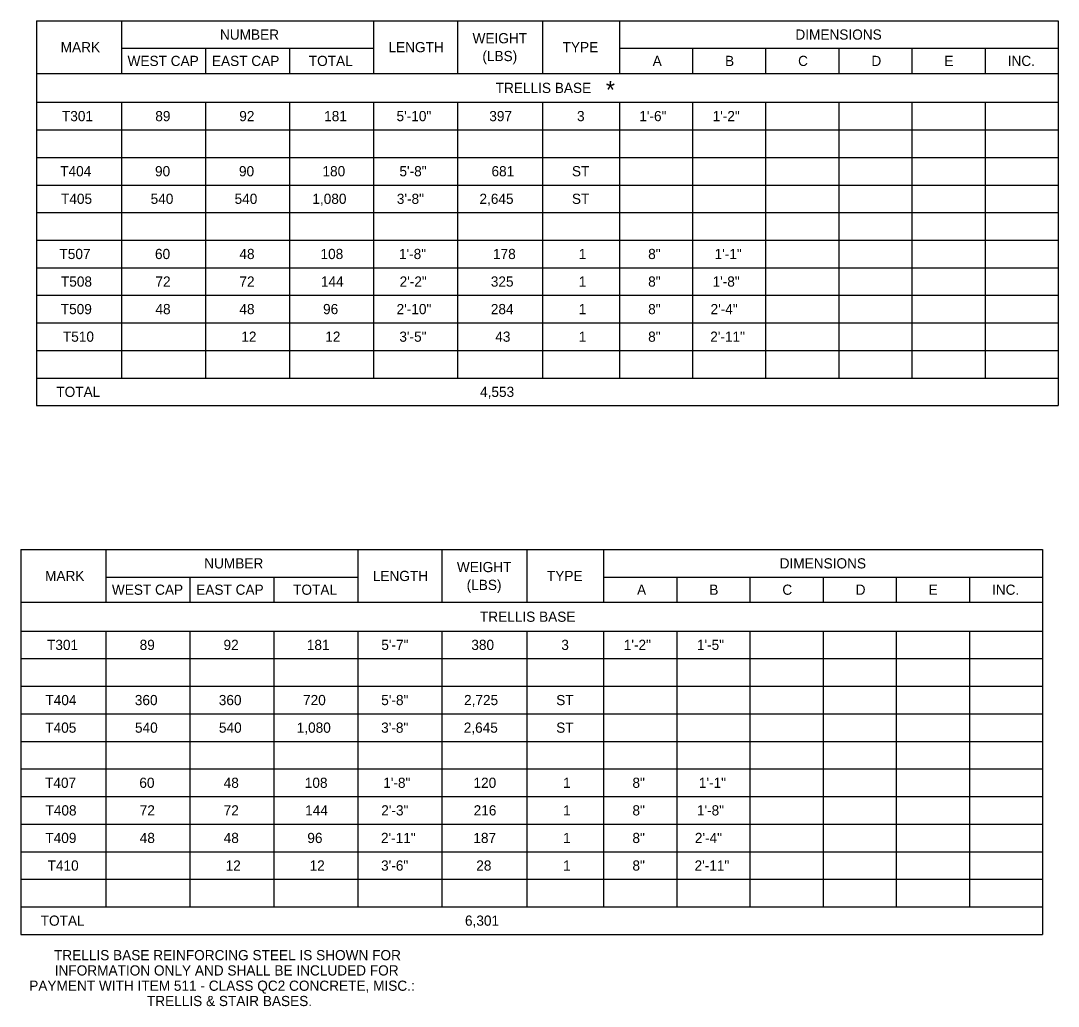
# Model space of a CAD drawing. Extents: x -47.5 to 51.5, y 0.9 to 23.7.
# Drawn here: x 37.25 to 51.5, y 10.13 to 23.67 of the extents above; entities that cross this region are included whole.
import ezdxf

# ---------------------------------------------------------------- set-up
doc = ezdxf.new("R2010")
doc.units = 0
for name, color, linetype in [('BR_P_Gen_Text', 7, 'Continuous'), ('BR_X_Slab_Const_Joint', 7, 'Continuous'), ('BR_X_Slab_Object', 7, 'Continuous')]:
    doc.layers.add(name, color=color, linetype=linetype)

msp = doc.modelspace()

# ---------------------------------------------------------------- linework, layer by layer
at = {"layer": 'BR_X_Slab_Object'}
for p, q in [((37.463, 23.668), (51.496, 23.668)), ((37.463, 23.668), (37.463, 18.381)), ((38.632, 23.668), (38.632, 22.943)), ((42.091, 23.668), (42.091, 22.943)), ((43.244, 23.668), (43.244, 22.943)), ((44.414, 23.668), (44.414, 22.943)), ((45.468, 23.668), (45.468, 22.943)), ((51.496, 23.668), (51.496, 18.381)), ((38.632, 23.289), (42.091, 23.289)), ((39.785, 23.289), (39.785, 22.943)), ((40.938, 23.289), (40.938, 22.943)), ((45.468, 23.289), (51.496, 23.289)), ((46.472, 23.289), (46.472, 22.943)), ((47.477, 23.289), (47.477, 22.943)), ((48.482, 23.289), (48.482, 22.943)), ((49.486, 23.289), (49.486, 22.943)), ((50.491, 23.289), (50.491, 22.943)), ((37.463, 22.943), (51.496, 22.943)), ((37.463, 22.548), (51.496, 22.548)), ((38.632, 22.548), (38.632, 18.76)), ((39.785, 22.548), (39.785, 18.76)), ((40.938, 22.548), (40.938, 18.76)), ((42.091, 22.548), (42.091, 18.76)), ((43.244, 22.548), (43.244, 18.76)), ((44.414, 22.548), (44.414, 18.76)), ((45.468, 22.548), (45.468, 18.76)), ((46.472, 22.548), (46.472, 18.76)), ((47.477, 22.548), (47.477, 18.76)), ((48.482, 22.548), (48.482, 18.76)), ((49.486, 22.548), (49.486, 18.76)), ((50.491, 22.548), (50.491, 18.76)), ((37.463, 22.169), (51.496, 22.169)), ((37.463, 21.79), (51.496, 21.79)), ((37.463, 21.411), (51.496, 21.411)), ((37.463, 21.032), (51.496, 21.032)), ((37.463, 20.654), (51.496, 20.654)), ((37.463, 20.275), (51.496, 20.275)), ((37.463, 19.896), (51.496, 19.896)), ((37.463, 19.517), (51.496, 19.517)), ((37.463, 19.138), (51.496, 19.138)), ((37.463, 18.76), (51.496, 18.76)), ((37.463, 18.381), (51.496, 18.381)), ((37.247, 16.403), (51.28, 16.403)), ((37.247, 16.403), (37.247, 11.116)), ((38.417, 16.403), (38.417, 15.679)), ((41.875, 16.403), (41.875, 15.679)), ((43.028, 16.403), (43.028, 15.679)), ((44.198, 16.403), (44.198, 15.679)), ((45.252, 16.403), (45.252, 15.679)), ((51.28, 16.403), (51.28, 11.116)), ((38.417, 16.025), (41.875, 16.025)), ((39.57, 16.025), (39.57, 15.679)), ((40.723, 16.025), (40.723, 15.679)), ((45.252, 16.025), (51.28, 16.025)), ((46.257, 16.025), (46.257, 15.679)), ((47.261, 16.025), (47.261, 15.679)), ((48.266, 16.025), (48.266, 15.679)), ((49.271, 16.025), (49.271, 15.679)), ((50.275, 16.025), (50.275, 15.679)), ((37.247, 15.679), (51.28, 15.679)), ((37.247, 15.283), (51.28, 15.283)), ((38.417, 15.283), (38.417, 11.495)), ((39.57, 15.283), (39.57, 11.495)), ((40.723, 15.283), (40.723, 11.495)), ((41.875, 15.283), (41.875, 11.495)), ((43.028, 15.283), (43.028, 11.495)), ((44.198, 15.283), (44.198, 11.495)), ((45.252, 15.283), (45.252, 11.495)), ((46.257, 15.283), (46.257, 11.495)), ((47.261, 15.283), (47.261, 11.495)), ((48.266, 15.283), (48.266, 11.495)), ((49.271, 15.283), (49.271, 11.495)), ((50.275, 15.283), (50.275, 11.495)), ((37.247, 14.905), (51.28, 14.905)), ((37.247, 14.526), (51.28, 14.526)), ((37.247, 14.147), (51.28, 14.147)), ((37.247, 13.768), (51.28, 13.768)), ((37.247, 13.389), (51.28, 13.389)), ((37.247, 13.01), (51.28, 13.01)), ((37.247, 12.632), (51.28, 12.632)), ((37.247, 12.253), (51.28, 12.253)), ((37.247, 11.874), (51.28, 11.874)), ((37.247, 11.495), (51.28, 11.495)), ((37.247, 11.116), (51.28, 11.116))]:
    msp.add_line(p, q, dxfattribs=at)

# ---------------------------------------------------------------- texts
at = {"layer": 'BR_P_Gen_Text'}
for s, p in [('NUMBER', (39.983, 23.408)), ('DIMENSIONS', (47.886, 23.408)), ('MARK', (37.796, 23.235)), ('LENGTH', (42.297, 23.235)), ('WEIGHT', (43.452, 23.358)), ('TYPE', (44.689, 23.235)), ('(LBS)', (43.587, 23.113)), ('WEST CAP', (38.714, 23.046)), ('EAST CAP', (39.873, 23.046)), ('TOTAL', (41.203, 23.046)), ('A', (45.926, 23.046)), ('B', (46.92, 23.046)), ('C', (47.923, 23.046)), ('D', (48.93, 23.046)), ('E', (49.932, 23.046)), ('INC.', (50.802, 23.046)), ('TRELLIS BASE', (43.77, 22.675)), ('T301', (37.813, 22.288)), ('89', (39.095, 22.288)), ('92', (40.248, 22.288)), ('181', (41.414, 22.288)), ('5\'-10"', (42.408, 22.288)), ('397', (43.682, 22.288)), ('3', (44.887, 22.288)), ('1\'-6"', (45.742, 22.288)), ('1\'-2"', (46.749, 22.288)), ('90', (39.091, 21.531)), ('90', (40.244, 21.531)), ('180', (41.391, 21.531)), ('5\'-8"', (42.448, 21.531)), ('ST', (44.817, 21.531)), ('T405', (37.8, 21.152)), ('540', (39.031, 21.152)), ('540', (40.184, 21.152)), ('1,080', (41.252, 21.152)), ('3\'-8"', (42.412, 21.152)), ('2,645', (43.547, 21.152)), ('ST', (44.817, 21.152)), ('T507', (37.779, 20.394)), ('60', (39.091, 20.394)), ('48', (40.25, 20.394)), ('108', (41.364, 20.394)), ('1\'-8"', (42.441, 20.394)), ('178', (43.733, 20.394)), ('1', (44.911, 20.394)), ('8"', (45.864, 20.394)), ('1\'-1"', (46.776, 20.394)), ('T508', (37.799, 20.015)), ('72', (39.097, 20.015)), ('72', (40.25, 20.015)), ('144', (41.369, 20.015)), ('2\'-2"', (42.45, 20.015)), ('325', (43.703, 20.015)), ('1', (44.911, 20.015)), ('8"', (45.864, 20.015)), ('1\'-8"', (46.748, 20.015)), ('T509', (37.797, 19.637)), ('48', (39.097, 19.637)), ('48', (40.25, 19.637)), ('96', (41.399, 19.637)), ('2\'-10"', (42.409, 19.637)), ('284', (43.703, 19.637)), ('1', (44.911, 19.637)), ('8"', (45.864, 19.637)), ('2\'-4"', (46.721, 19.637)), ('T510', (37.826, 19.258)), ('12', (40.276, 19.258)), ('12', (41.429, 19.258)), ('3\'-5"', (42.447, 19.258)), ('43', (43.764, 19.258)), ('1', (44.911, 19.258)), ('8"', (45.864, 19.258)), ('2\'-11"', (46.716, 19.258)), ('TOTAL', (37.736, 18.5)), ('4,553', (43.555, 18.5)), ('NUMBER', (39.767, 16.144)), ('DIMENSIONS', (47.67, 16.144)), ('MARK', (37.581, 15.971)), ('LENGTH', (42.082, 15.971)), ('WEIGHT', (43.237, 16.093)), ('TYPE', (44.474, 15.971)), ('(LBS)', (43.371, 15.848)), ('WEST CAP', (38.499, 15.782)), ('EAST CAP', (39.657, 15.782)), ('TOTAL', (40.988, 15.782)), ('A', (45.711, 15.782)), ('B', (46.704, 15.782)), ('C', (47.707, 15.782)), ('D', (48.714, 15.782)), ('E', (49.716, 15.782)), ('INC.', (50.586, 15.782)), ('TRELLIS BASE', (43.554, 15.411)), ('T301', (37.608, 15.024)), ('89', (38.88, 15.024)), ('92', (40.032, 15.024)), ('181', (41.176, 15.024)), ('5\'-7"', (42.199, 15.024)), ('380', (43.435, 15.024)), ('3', (44.671, 15.024)), ('1\'-2"', (45.529, 15.024)), ('1\'-5"', (46.533, 15.024)), ('T404', (37.586, 14.266)), ('360', (38.814, 14.266)), ('360', (39.967, 14.266)), ('720', (41.124, 14.266)), ('5\'-8"', (42.198, 14.266)), ('2,725', (43.335, 14.266)), ('ST', (44.601, 14.266)), ('T405', (37.584, 13.887)), ('540', (38.816, 13.887)), ('540', (39.969, 13.887)), ('1,080', (41.037, 13.887)), ('3\'-8"', (42.197, 13.887)), ('2,645', (43.331, 13.887)), ('ST', (44.601, 13.887)), ('T407', (37.581, 13.13)), ('60', (38.876, 13.13)), ('48', (40.034, 13.13)), ('108', (41.148, 13.13)), ('1\'-8"', (42.225, 13.13)), ('120', (43.465, 13.13)), ('1', (44.696, 13.13)), ('8"', (45.648, 13.13)), ('1\'-1"', (46.56, 13.13)), ('T408', (37.587, 12.751)), ('72', (38.881, 12.751)), ('72', (40.034, 12.751)), ('144', (41.153, 12.751)), ('2\'-3"', (42.198, 12.751)), ('216', (43.467, 12.751)), ('1', (44.696, 12.751)), ('8"', (45.648, 12.751)), ('1\'-8"', (46.533, 12.751)), ('T409', (37.585, 12.372)), ('48', (38.881, 12.372)), ('48', (40.034, 12.372)), ('96', (41.183, 12.372)), ('2\'-11"', (42.194, 12.372)), ('187', (43.463, 12.372)), ('1', (44.696, 12.372)), ('8"', (45.648, 12.372)), ('2\'-4"', (46.505, 12.372)), ('T410', (37.616, 11.993)), ('12', (40.061, 11.993)), ('12', (41.214, 11.993)), ('3\'-6"', (42.196, 11.993)), ('28', (43.503, 11.993)), ('1', (44.696, 11.993)), ('8"', (45.648, 11.993)), ('2\'-11"', (46.501, 11.993)), ('TOTAL', (37.521, 11.236)), ('6,301', (43.348, 11.236))]:
    msp.add_text(s, height=0.14, dxfattribs=at).set_placement(p)
at = {"layer": 'BR_X_Slab_Const_Joint'}
for s, height, p in [('*', 0.24, (45.283, 22.6)), ('T404', 0.14, (37.789, 21.531)), ('681', 0.14, (43.712, 21.531)), ('TRELLIS BASE REINFORCING STEEL IS SHOWN FOR', 0.14, (37.704, 10.762)), ('INFORMATION ONLY AND SHALL BE INCLUDED FOR ', 0.14, (37.714, 10.552)), ('PAYMENT WITH ITEM 511 - CLASS QC2 CONCRETE, MISC.:', 0.14, (37.364, 10.342)), ('TRELLIS & STAIR BASES.', 0.14, (38.98, 10.132))]:
    msp.add_text(s, height=height, dxfattribs=at).set_placement(p)

doc.saveas('drawing.dxf')
